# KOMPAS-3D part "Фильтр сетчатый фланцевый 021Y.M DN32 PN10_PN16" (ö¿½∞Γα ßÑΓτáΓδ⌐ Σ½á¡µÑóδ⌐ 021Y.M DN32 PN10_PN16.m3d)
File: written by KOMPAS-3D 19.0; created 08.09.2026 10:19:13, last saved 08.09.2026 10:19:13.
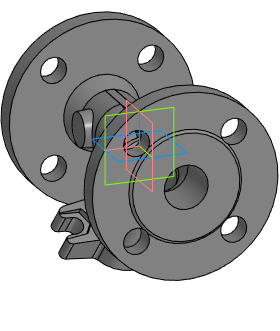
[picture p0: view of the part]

Document properties: Автор: Энергия; Полное имя файла: Z:\3.Личные\sachek\Dendor\_3D для проектировщиков\8.2 Фильтр сетчатый 021Y.M\021Y.M_STP\Фильтр сетчатый фланцевый 021Y.M DN32 PN10_PN16.m3d

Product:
- Part/product: Фильтр сетчатый фланцевый 021Y.M DN32 PN10_PN16

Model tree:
1. Операция без истории:1  (labels: Фильтр сетчатый фланцевый 021Y.M DN32 PN10_PN16)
